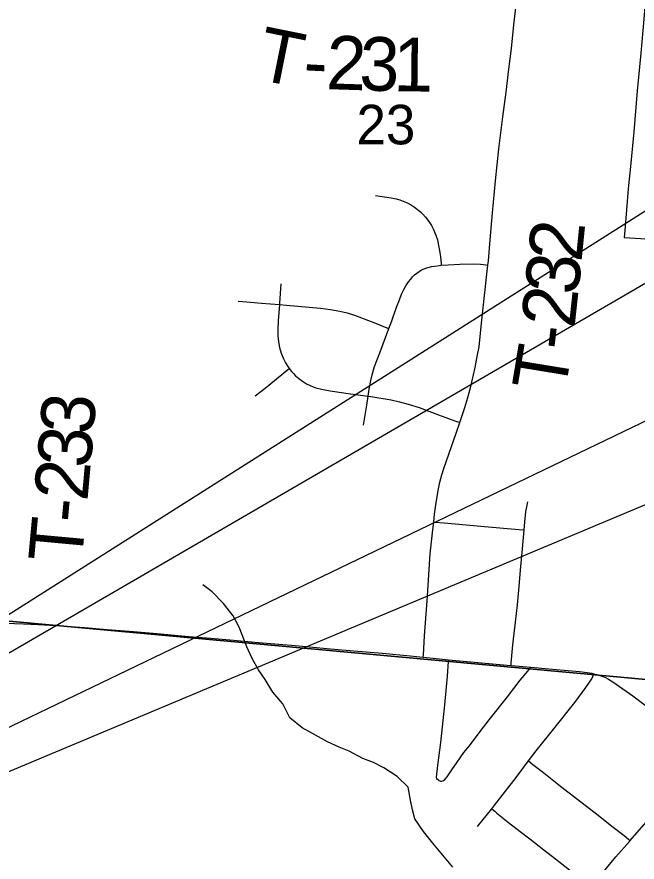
# Model space of a CAD drawing. Extents: x 0 to 34, y 0 to 22.
# Drawn here: x 5.23 to 5.887, y 18.097 to 18.991 of the extents above; entities that cross this region are included whole.
import ezdxf

# ---------------------------------------------------------------- set-up
doc = ezdxf.new("R2010")
doc.units = 0
for name, color, linetype in [('GM_X_County_Road', 7, 'Continuous'), ('GM_X_Minor_River', 7, 'Continuous'), ('GM_X_Section', 7, 'Continuous'), ('GM_X_Section_Text', 7, 'Continuous'), ('GM_X_Township_Road', 7, 'Continuous'), ('GM_X_Township_Road_Text', 7, 'Continuous'), ('SH_Text', 7, 'Continuous')]:
    doc.layers.add(name, color=color, linetype=linetype)

msp = doc.modelspace()

# ---------------------------------------------------------------- linework, layer by layer
at = {"layer": 'GM_X_County_Road'}
msp.add_line((5.75334, 18.30449), (5.77414, 18.30273), dxfattribs=at)
for points in [[(5.19391, 18.35046), (5.21797, 18.34949), (5.23709, 18.34867), (5.25284, 18.34799), (5.27743, 18.34657), (5.30171, 18.34484), (5.32594, 18.3428), (5.3538, 18.34051), (5.38266, 18.33798), (5.41219, 18.33544), (5.43537, 18.33353), (5.45965, 18.33124), (5.48609, 18.32902), (5.52477, 18.32574), (5.56209, 18.32235), (5.58681, 18.32012), (5.61708, 18.31747), (5.64645, 18.31476)], [(5.64645, 18.31476), (5.6533, 18.31413), (5.66045, 18.31335)], [(5.66045, 18.31335), (5.67097, 18.31221), (5.68722, 18.31063)], [(5.68722, 18.31063), (5.70267, 18.30912), (5.74542, 18.30517), (5.75334, 18.30449)], [(5.77414, 18.30273), (5.79344, 18.30109), (5.82575, 18.29819), (5.83372, 18.29726), (5.83879, 18.29633), (5.84103, 18.2958)], [(5.84103, 18.2958), (5.84398, 18.2951), (5.84824, 18.2938), (5.85244, 18.29213), (5.85652, 18.29021), (5.86121, 18.28737), (5.88229, 18.27242), (5.89532, 18.26266), (5.9018, 18.25791)]]:
    msp.add_lwpolyline(points, dxfattribs=at)
at = {"layer": 'GM_X_Minor_River'}
msp.add_lwpolyline([(5.69153, 18.09121), (5.67058, 18.11653), (5.66048, 18.12881), (5.65153, 18.14221), (5.64899, 18.15174), (5.64684, 18.16203), (5.64435, 18.17574), (5.63272, 18.18727), (5.61878, 18.19618), (5.60784, 18.202), (5.59649, 18.20632), (5.58178, 18.21409), (5.57119, 18.21802), (5.55911, 18.22386), (5.54628, 18.23085), (5.53233, 18.23862), (5.51916, 18.24903), (5.51175, 18.26394), (5.50127, 18.27622), (5.49309, 18.28962), (5.486, 18.29997), (5.47931, 18.31183), (5.47377, 18.32443), (5.46567, 18.34505), (5.45899, 18.3573), (5.4489, 18.37034), (5.4369, 18.38264), (5.42712, 18.38998)], dxfattribs=at)
at = {"layer": 'GM_X_Section'}
for points in [[(5.2197, 19.35965), (6.2677, 19.26674), (6.17707, 18.26412), (5.13301, 18.35974)], [(5.13301, 18.35974), (6.17707, 18.26412), (6.07115, 17.24621), (5.04874, 17.32193)]]:
    msp.add_lwpolyline(points, close=True, dxfattribs=at)
at = {"layer": 'GM_X_Township_Road'}
msp.add_line((5.71773, 18.13421), (5.73286, 18.15296), dxfattribs=at)
for points in [[(5.72881, 18.72821), (5.7293, 18.733), (5.73126, 18.75514), (5.73378, 18.78346), (5.73683, 18.81759), (5.74054, 18.85124), (5.74468, 18.88518), (5.74811, 18.91134), (5.7511, 18.93564), (5.75362, 18.95766), (5.75637, 18.98244), (5.7582, 19.00056), (5.75866, 19.00732), (5.75889, 19.01072)], [(5.89579, 19.01105), (5.89379, 18.98853), (5.89075, 18.9525), (5.88688, 18.91273), (5.88314, 18.86949), (5.87994, 18.83613), (5.87741, 18.8089), (5.87553, 18.7869), (5.8738, 18.765), (5.87318, 18.75743), (5.89056, 18.7563), (5.93818, 18.75256), (5.97202, 18.74968), (6.0014, 18.74707), (6.01393, 18.74573), (6.01676, 18.7455), (6.01643, 18.76132), (6.01355, 18.80765), (6.01056, 18.85462), (6.008, 18.89594), (6.00591, 18.93343), (6.0033, 18.97516), (6.00181, 18.99971)], [(5.60974, 18.80191), (5.62629, 18.79956), (5.63167, 18.79854), (5.63553, 18.79738), (5.639, 18.79611), (5.64264, 18.79463), (5.64676, 18.79237), (5.65094, 18.78975), (5.65443, 18.78709), (5.6575, 18.78463), (5.65989, 18.78211), (5.66269, 18.7789), (5.66624, 18.77432), (5.66904, 18.77037), (5.67095, 18.76661), (5.67375, 18.75998), (5.67529, 18.75489), (5.67662, 18.7492), (5.67764, 18.74373), (5.67853, 18.73697), (5.67928, 18.7298), (5.67946, 18.72807)], [(5.62403, 18.66124), (5.62675, 18.66839), (5.63217, 18.68371), (5.6351, 18.69171), (5.63751, 18.69757), (5.63957, 18.7017), (5.64207, 18.70626), (5.64491, 18.71073), (5.64707, 18.71351), (5.64909, 18.7158), (5.65121, 18.71795), (5.65352, 18.71992), (5.65597, 18.72168), (5.65857, 18.72319), (5.66131, 18.72445), (5.66417, 18.72545), (5.66944, 18.72666), (5.67521, 18.72769), (5.67946, 18.72807)], [(5.67946, 18.72807), (5.68665, 18.72872), (5.69904, 18.72932), (5.71319, 18.72958), (5.72082, 18.72917), (5.72668, 18.72847), (5.72881, 18.72821)], [(5.6991, 18.56168), (5.70063, 18.56614), (5.70442, 18.57772), (5.70749, 18.58816), (5.71061, 18.59997), (5.71371, 18.61236), (5.71543, 18.62004), (5.71761, 18.63151), (5.7194, 18.64182), (5.7222, 18.66683), (5.72518, 18.69619), (5.72781, 18.71855), (5.72881, 18.72821)], [(5.50978, 18.70858), (5.50815, 18.68818), (5.50802, 18.68655)], [(5.46433, 18.68999), (5.47369, 18.6893), (5.48906, 18.68803), (5.50802, 18.68655)], [(5.50802, 18.68655), (5.50668, 18.66942), (5.50629, 18.65969), (5.50645, 18.65344), (5.507, 18.64719), (5.5082, 18.641), (5.51007, 18.63498), (5.51251, 18.6292), (5.5146, 18.62501), (5.51704, 18.62093), (5.5185, 18.61894)], [(5.50802, 18.68655), (5.51572, 18.68595), (5.55161, 18.68276), (5.56211, 18.68139), (5.57203, 18.67973), (5.57993, 18.67794), (5.58768, 18.67527), (5.60998, 18.667), (5.62193, 18.6621), (5.62403, 18.66124)], [(5.6021, 18.58968), (5.60317, 18.59687), (5.6049, 18.60616), (5.60627, 18.61215), (5.60891, 18.62099), (5.61424, 18.63552), (5.62403, 18.66124)], [(5.48255, 18.58994), (5.49316, 18.59809), (5.51668, 18.61745), (5.5185, 18.61894)], [(5.5185, 18.61894), (5.52079, 18.61586), (5.5229, 18.61349), (5.5252, 18.6113), (5.5288, 18.60831), (5.53263, 18.60554), (5.53689, 18.6028), (5.54078, 18.60075), (5.54369, 18.59949), (5.54666, 18.59844), (5.55275, 18.59684), (5.56196, 18.59518), (5.58349, 18.59222), (5.6021, 18.58968)], [(5.59723, 18.55899), (5.60067, 18.58017), (5.6021, 18.58968)], [(5.6021, 18.58968), (5.60497, 18.58929), (5.62631, 18.58558), (5.63537, 18.58364), (5.64431, 18.58128), (5.65606, 18.57754), (5.67636, 18.56996), (5.69385, 18.5636), (5.6991, 18.56168)], [(5.67145, 18.45649), (5.67244, 18.46467), (5.67415, 18.47703), (5.67646, 18.49149), (5.67797, 18.49857), (5.68007, 18.50623), (5.68217, 18.51293), (5.68744, 18.52829), (5.69525, 18.55043), (5.6991, 18.56168)], [(5.76711, 18.448), (5.76778, 18.45616), (5.76908, 18.46732), (5.76989, 18.47265), (5.771, 18.47779)], [(5.66045, 18.31335), (5.66061, 18.31604), (5.6618, 18.33586), (5.66437, 18.37292), (5.66772, 18.4229), (5.67006, 18.44503), (5.67145, 18.45649)], [(5.67145, 18.45649), (5.67296, 18.45635), (5.68263, 18.45544), (5.72128, 18.45212), (5.76167, 18.44849), (5.76711, 18.448)], [(5.75334, 18.30449), (5.75358, 18.30719), (5.7553, 18.32661), (5.75811, 18.35047), (5.76002, 18.36877), (5.76144, 18.38437), (5.76369, 18.40933), (5.76549, 18.42804), (5.76711, 18.448)], [(5.67681, 18.1827), (5.67548, 18.18377), (5.67467, 18.18485), (5.67431, 18.18648), (5.67597, 18.19892), (5.6789, 18.22326), (5.68317, 18.26281), (5.68589, 18.29325), (5.68708, 18.30872), (5.68722, 18.31063)], [(5.67681, 18.1827), (5.67845, 18.18219), (5.68018, 18.18224), (5.68166, 18.1827), (5.6833, 18.18382), (5.6858, 18.18674), (5.69051, 18.19414), (5.69612, 18.20227), (5.70318, 18.21238), (5.7092, 18.21973), (5.72049, 18.23476), (5.73011, 18.24713), (5.74967, 18.27159), (5.76309, 18.28893), (5.77093, 18.29872), (5.77414, 18.30273)], [(5.77189, 18.20356), (5.78005, 18.21434), (5.79988, 18.23946), (5.82065, 18.26551), (5.83263, 18.28131), (5.83884, 18.29062), (5.84001, 18.29308), (5.84072, 18.29496), (5.84103, 18.2958)], [(5.87946, 18.1194), (5.91568, 18.16088), (5.93212, 18.17975), (5.94434, 18.19399), (5.95554, 18.207), (5.9604, 18.21247), (5.96152, 18.21372)], [(5.73286, 18.15296), (5.73628, 18.1572), (5.75858, 18.18595), (5.77189, 18.20356)], [(5.77189, 18.20356), (5.77647, 18.19995), (5.78617, 18.19227), (5.8055, 18.17694), (5.82262, 18.16379), (5.84223, 18.14875), (5.86157, 18.1334), (5.87298, 18.12458), (5.87768, 18.12083), (5.87946, 18.1194)], [(5.73286, 18.15296), (5.73598, 18.15025), (5.73835, 18.14819), (5.75062, 18.13841), (5.76308, 18.12886), (5.77302, 18.12117), (5.78796, 18.10965), (5.80032, 18.09996), (5.81518, 18.08834), (5.83133, 18.07611), (5.83524, 18.07285), (5.83698, 18.07085), (5.83897, 18.0683), (5.84024, 18.06668)], [(5.84024, 18.06668), (5.84223, 18.07226), (5.84387, 18.07576), (5.84643, 18.0803), (5.85425, 18.09003), (5.86436, 18.10195), (5.87868, 18.11849), (5.87946, 18.1194)]]:
    msp.add_lwpolyline(points, dxfattribs=at)
at = {"layer": 'SH_Text'}
for points in [[(9.2218, 20.89411), (4.45803, 17.87452), (9.2218, 20.64169)], [(9.24529, 20.17502), (4.46592, 17.8756), (9.24529, 19.87959)]]:
    msp.add_lwpolyline(points, close=True, dxfattribs=at)

# ---------------------------------------------------------------- texts
at = {"layer": 'GM_X_Section_Text'}
msp.add_text('23', height=0.041856, rotation=0.00001, dxfattribs=at).set_placement((5.5897, 18.85609))
at = {"layer": 'GM_X_Township_Road_Text'}
for s, rotation, p in [('T', 348.56736, (5.48185, 18.92541)), ('2', 358.1401, (5.55708, 18.9146)), ('3', 358.23415, (5.59216, 18.91346)), ('1', 359.36257, (5.62836, 18.91236)), ('-', 357.07898, (5.53263, 18.91584)), ('2', 84.24046, (5.82774, 18.73066)), ('3', 84.16097, (5.82417, 18.69575)), ('2', 83.82323, (5.82036, 18.6606)), ('-', 83.2797, (5.81757, 18.63683)), ('T', 80.6807, (5.81029, 18.59211)), ('3', 85.52964, (5.31105, 18.54812)), ('3', 84.98747, (5.30794, 18.51267)), ('2', 84.81566, (5.30476, 18.47763)), ('-', 84.75993, (5.30263, 18.45434)), ('T', 84.75551, (5.29874, 18.41201))]:
    msp.add_text(s, height=0.05682, rotation=rotation, dxfattribs=at).set_placement(p)

doc.saveas('drawing.dxf')
